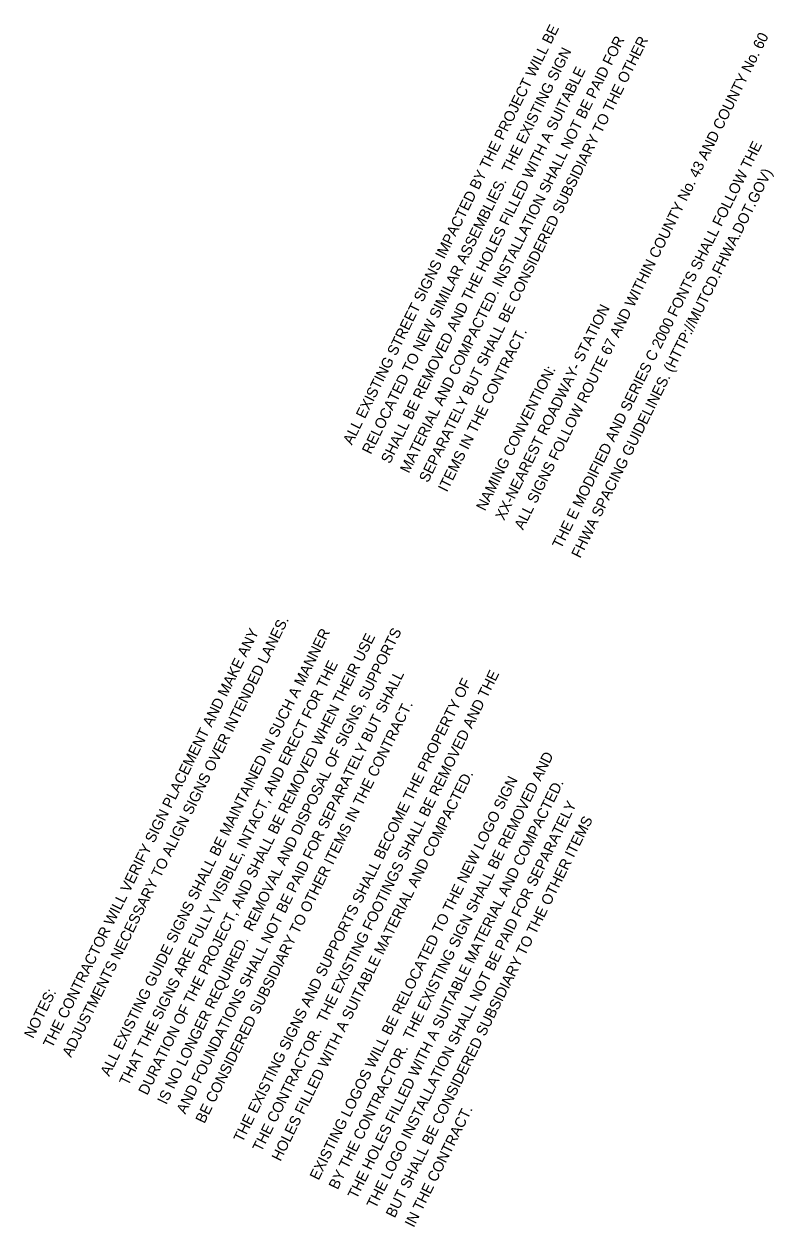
# Model space of a CAD drawing. Extents: x 1288247 to 1295361, y 218673 to 226414.
# Drawn here: x 1289014 to 1289508, y 220521 to 221314 of the extents above; entities that cross this region are included whole.
import ezdxf

# ---------------------------------------------------------------- set-up
doc = ezdxf.new("R2010")
doc.units = 0
doc.layers.add('R_Annotation', color=7, linetype='Continuous')

msp = doc.modelspace()

# ---------------------------------------------------------------- texts
at = {"layer": 'R_Annotation'}
for s, p in [('ALL EXISTING STREET SIGNS IMPACTED BY THE PROJECT WILL BE ', (1289229.66, 221036.26)), ('MATERIAL AND COMPACTED. INSTALLATION SHALL NOT BE PAID FOR ', (1289267.27, 221017.58)), ('SEPARATELY BUT SHALL BE CONSIDERED SUBSIDIARY TO THE OTHER', (1289279.81, 221011.35)), ('ALL SIGNS FOLLOW ROUTE 67 AND WITHIN COUNTY No. 43 AND COUNTY No. 60', (1289342.51, 220980.22)), ('RELOCATED TO NEW SIMILAR ASSEMBLIES.  THE EXISTING SIGN ', (1289242.2, 221030.04)), ('SHALL BE REMOVED AND THE HOLES FILLED WITH A SUITABLE ', (1289254.74, 221023.81)), ('THE E MODIFIED AND SERIES C 2000 FONTS SHALL FOLLOW THE', (1289367.59, 220967.77)), ('FHWA SPACING GUIDELINES. (HTTP://MUTCD.FHWA.DOT.GOV)', (1289380.13, 220961.54)), ('XX-NEAREST ROADWAY- STATION', (1289329.97, 220986.45)), ('ITEMS IN THE CONTRACT.', (1289292.35, 221005.13)), ('NAMING CONVENTION:', (1289317.43, 220992.67)), ('THE CONTRACTOR WILL VERIFY SIGN PLACEMENT AND MAKE ANY', (1289032.2, 220638.64)), ('ADJUSTMENTS NECESSARY TO ALIGN SIGNS OVER INTENDED LANES.', (1289044.74, 220632.41)), ('ALL EXISTING GUIDE SIGNS SHALL BE MAINTAINED IN SUCH A MANNER', (1289069.82, 220619.96)), ('DURATION OF THE PROJECT, AND SHALL BE REMOVED WHEN THEIR USE', (1289094.9, 220607.51)), ('IS NO LONGER REQUIRED.  REMOVAL AND DISPOSAL OF SIGNS, SUPPORTS', (1289107.43, 220601.28)), ('THAT THE SIGNS ARE FULLY VISIBLE, INTACT, AND ERECT FOR THE', (1289082.36, 220613.73)), ('AND FOUNDATIONS SHALL NOT BE PAID FOR SEPARATELY BUT SHALL', (1289119.97, 220595.05)), ('THE CONTRACTOR.  THE EXISTING FOOTINGS SHALL BE REMOVED AND THE ', (1289170.13, 220570.14)), ('THE EXISTING SIGNS AND SUPPORTS SHALL BECOME THE PROPERTY OF ', (1289157.59, 220576.37)), ('BE CONSIDERED SUBSIDIARY TO OTHER ITEMS IN THE CONTRACT.', (1289132.51, 220588.83)), ('BY THE CONTRACTOR.  THE EXISTING SIGN SHALL BE REMOVED AND ', (1289220.29, 220545.24)), ('HOLES FILLED WITH A SUITABLE MATERIAL AND COMPACTED.', (1289182.67, 220563.92)), ('EXISTING LOGOS WILL BE RELOCATED TO THE NEW LOGO SIGN', (1289207.75, 220551.46)), ('THE HOLES FILLED WITH A SUITABLE MATERIAL AND COMPACTED.', (1289232.82, 220539.01)), ('THE LOGO INSTALLATION SHALL NOT BE PAID FOR SEPARATELY', (1289245.36, 220532.78)), ('BUT SHALL BE CONSIDERED SUBSIDIARY TO THE OTHER ITEMS ', (1289257.9, 220526.56)), ('NOTES:', (1289019.66, 220644.87)), ('IN THE CONTRACT.', (1289270.44, 220520.33))]:
    msp.add_text(s, height=7, rotation=63.59131, dxfattribs=at).set_placement(p)

doc.saveas('drawing.dxf')
